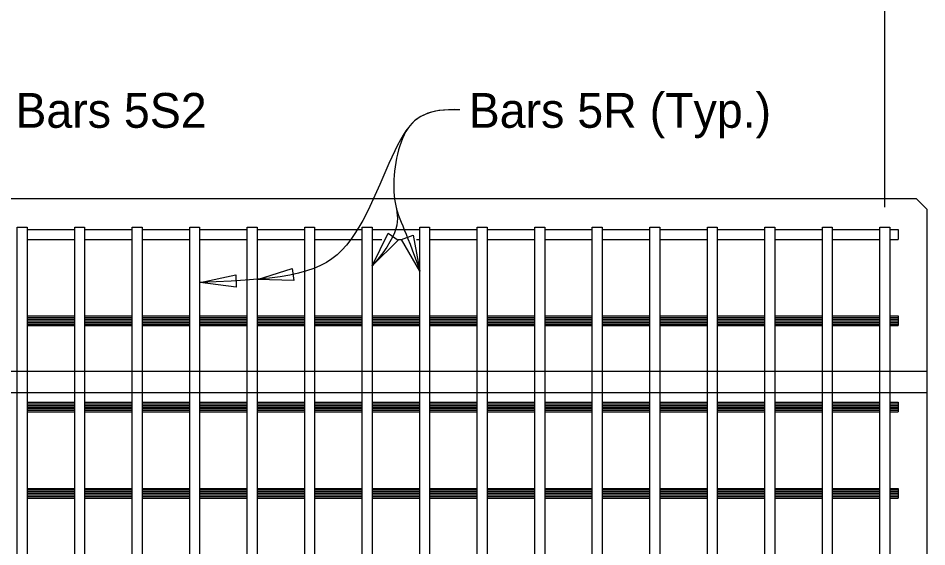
# Model space of a CAD drawing. Extents: x 120587.5 to 120659.6, y 120683.4 to 120715.5.
# Drawn here: x 120592.74 to 120598, y 120702.4 to 120705.47 of the extents above; entities that cross this region are included whole.
import ezdxf

# ---------------------------------------------------------------- set-up
doc = ezdxf.new("R2010")
doc.units = 0
for name, color, linetype in [('AdhocPoint_dp', 7, 'Continuous'), ('Border', 7, 'Continuous'), ('PlotBorder_dp', 7, 'Continuous'), ('TextMisc', 7, 'Continuous')]:
    doc.layers.add(name, color=color, linetype=linetype)

msp = doc.modelspace()

# ---------------------------------------------------------------- linework, layer by layer
at = {"layer": 'AdhocPoint_dp'}
msp.add_line((120597.7581, 120704.3707), (120597.7581, 120706.3004), dxfattribs=at)
for points in [[(120594.7867, 120704.0299), (120594.8793, 120704.2197), (120594.9366, 120704.1786)], [(120595.0627, 120703.9997), (120594.9577, 120704.183), (120595.0239, 120704.2074)], [(120594.1226, 120703.951), (120594.3241, 120704.0146), (120594.3338, 120703.9447)], [(120593.7893, 120703.9341), (120593.996, 120703.9773), (120593.9988, 120703.9068)]]:
    msp.add_lwpolyline(points, close=True, dxfattribs=at)
for points in [[(120595.2949, 120704.9346), (120595.1103, 120704.9415), (120594.9377, 120704.8446), (120594.8852, 120704.3646), (120594.9784, 120704.2515), (120594.7867, 120704.0299)], [(120595.2949, 120704.9346), (120595.1103, 120704.9415), (120594.9377, 120704.8446), (120594.8852, 120704.3646), (120594.9784, 120704.2515), (120595.0627, 120703.9997)], [(120595.2949, 120704.9346), (120595.1197, 120704.9346), (120594.9534, 120704.8972), (120594.6845, 120704.0214), (120594.3179, 120703.952), (120593.7867, 120703.934)]]:
    msp.add_open_spline(points, degree=3, dxfattribs=at)
at = {"layer": 'Border'}
for p, q in [((120592.7867, 120704.2407), (120593.0627, 120704.2407)), ((120593.12, 120704.2407), (120593.3961, 120704.2407)), ((120593.4534, 120704.2407), (120593.7294, 120704.2407)), ((120593.7867, 120704.2407), (120594.0627, 120704.2407)), ((120594.12, 120704.2407), (120594.3961, 120704.2407)), ((120594.4534, 120704.2407), (120594.7294, 120704.2407)), ((120594.7867, 120704.2407), (120595.0627, 120704.2407)), ((120595.12, 120704.2407), (120595.3961, 120704.2407)), ((120595.4534, 120704.2407), (120595.7294, 120704.2407)), ((120595.7867, 120704.2407), (120596.0627, 120704.2407)), ((120596.12, 120704.2407), (120596.3961, 120704.2407)), ((120596.4534, 120704.2407), (120596.7294, 120704.2407)), ((120596.7867, 120704.2407), (120597.0627, 120704.2407)), ((120597.12, 120704.2407), (120597.3961, 120704.2407)), ((120597.4534, 120704.2407), (120597.7294, 120704.2407)), ((120597.7867, 120704.2407), (120597.8349, 120704.2407)), ((120597.8349, 120704.2407), (120597.8349, 120704.1834)), ((120592.7867, 120704.1834), (120593.0627, 120704.1834)), ((120593.12, 120704.1834), (120593.3961, 120704.1834)), ((120593.4534, 120704.1834), (120593.7294, 120704.1834)), ((120593.7867, 120704.1834), (120594.0627, 120704.1834)), ((120594.12, 120704.1834), (120594.3961, 120704.1834)), ((120594.4534, 120704.1834), (120594.7294, 120704.1834)), ((120594.7867, 120704.1834), (120594.8422, 120704.1834)), ((120594.9377, 120704.1834), (120594.9526, 120704.1834)), ((120595.0441, 120704.1834), (120595.0627, 120704.1834)), ((120595.12, 120704.1834), (120595.3961, 120704.1834)), ((120595.4534, 120704.1834), (120595.7294, 120704.1834)), ((120595.7867, 120704.1834), (120596.0627, 120704.1834)), ((120596.12, 120704.1834), (120596.3961, 120704.1834)), ((120596.4534, 120704.1834), (120596.7294, 120704.1834)), ((120596.7867, 120704.1834), (120597.0627, 120704.1834)), ((120597.12, 120704.1834), (120597.3961, 120704.1834)), ((120597.4534, 120704.1834), (120597.7294, 120704.1834)), ((120597.7867, 120704.1834), (120597.8349, 120704.1834)), ((120592.7867, 120703.7407), (120593.0627, 120703.7407)), ((120592.7867, 120703.7311), (120593.0627, 120703.7311)), ((120593.12, 120703.7407), (120593.3961, 120703.7407)), ((120593.12, 120703.7311), (120593.3961, 120703.7311)), ((120593.4534, 120703.7407), (120593.7294, 120703.7407)), ((120593.4534, 120703.7311), (120593.7294, 120703.7311)), ((120593.7867, 120703.7407), (120594.0627, 120703.7407)), ((120593.7867, 120703.7311), (120594.0627, 120703.7311)), ((120594.12, 120703.7407), (120594.3961, 120703.7407)), ((120594.12, 120703.7311), (120594.3961, 120703.7311)), ((120594.4534, 120703.7407), (120594.7294, 120703.7407)), ((120594.4534, 120703.7311), (120594.7294, 120703.7311)), ((120594.7867, 120703.7407), (120595.0627, 120703.7407)), ((120594.7867, 120703.7311), (120595.0627, 120703.7311)), ((120595.12, 120703.7407), (120595.3961, 120703.7407)), ((120595.12, 120703.7311), (120595.3961, 120703.7311)), ((120595.4534, 120703.7407), (120595.7294, 120703.7407)), ((120595.4534, 120703.7311), (120595.7294, 120703.7311)), ((120595.7867, 120703.7407), (120596.0627, 120703.7407)), ((120595.7867, 120703.7311), (120596.0627, 120703.7311)), ((120596.12, 120703.7407), (120596.3961, 120703.7407)), ((120596.12, 120703.7311), (120596.3961, 120703.7311)), ((120596.4534, 120703.7407), (120596.7294, 120703.7407)), ((120596.4534, 120703.7311), (120596.7294, 120703.7311)), ((120596.7867, 120703.7407), (120597.0627, 120703.7407)), ((120596.7867, 120703.7311), (120597.0627, 120703.7311)), ((120597.12, 120703.7407), (120597.3961, 120703.7407)), ((120597.12, 120703.7311), (120597.3961, 120703.7311)), ((120597.4534, 120703.7407), (120597.7294, 120703.7407)), ((120597.4534, 120703.7311), (120597.7294, 120703.7311)), ((120597.7867, 120703.7407), (120597.8349, 120703.7407)), ((120597.7867, 120703.7311), (120597.8349, 120703.7311)), ((120597.8349, 120703.7407), (120597.8349, 120703.6834)), ((120592.7867, 120703.7216), (120593.0627, 120703.7216)), ((120592.7867, 120703.712), (120593.0627, 120703.712)), ((120592.7867, 120703.7025), (120593.0627, 120703.7025)), ((120592.7867, 120703.6929), (120593.0627, 120703.6929)), ((120592.7867, 120703.6834), (120593.0627, 120703.6834)), ((120593.12, 120703.7216), (120593.3961, 120703.7216)), ((120593.12, 120703.712), (120593.3961, 120703.712)), ((120593.12, 120703.7025), (120593.3961, 120703.7025)), ((120593.12, 120703.6929), (120593.3961, 120703.6929)), ((120593.12, 120703.6834), (120593.3961, 120703.6834)), ((120593.4534, 120703.7216), (120593.7294, 120703.7216)), ((120593.4534, 120703.712), (120593.7294, 120703.712)), ((120593.4534, 120703.7025), (120593.7294, 120703.7025)), ((120593.4534, 120703.6929), (120593.7294, 120703.6929)), ((120593.4534, 120703.6834), (120593.7294, 120703.6834)), ((120593.7867, 120703.7216), (120594.0627, 120703.7216)), ((120593.7867, 120703.712), (120594.0627, 120703.712)), ((120593.7867, 120703.7025), (120594.0627, 120703.7025)), ((120593.7867, 120703.6929), (120594.0627, 120703.6929)), ((120593.7867, 120703.6834), (120594.0627, 120703.6834)), ((120594.12, 120703.7216), (120594.3961, 120703.7216)), ((120594.12, 120703.712), (120594.3961, 120703.712)), ((120594.12, 120703.7025), (120594.3961, 120703.7025)), ((120594.12, 120703.6929), (120594.3961, 120703.6929)), ((120594.12, 120703.6834), (120594.3961, 120703.6834)), ((120594.4534, 120703.7216), (120594.7294, 120703.7216)), ((120594.4534, 120703.712), (120594.7294, 120703.712)), ((120594.4534, 120703.7025), (120594.7294, 120703.7025)), ((120594.4534, 120703.6929), (120594.7294, 120703.6929)), ((120594.4534, 120703.6834), (120594.7294, 120703.6834)), ((120594.7867, 120703.7216), (120595.0627, 120703.7216)), ((120594.7867, 120703.712), (120595.0627, 120703.712)), ((120594.7867, 120703.7025), (120595.0627, 120703.7025)), ((120594.7867, 120703.6929), (120595.0627, 120703.6929)), ((120594.7867, 120703.6834), (120595.0627, 120703.6834)), ((120595.12, 120703.7216), (120595.3961, 120703.7216)), ((120595.12, 120703.712), (120595.3961, 120703.712)), ((120595.12, 120703.7025), (120595.3961, 120703.7025)), ((120595.12, 120703.6929), (120595.3961, 120703.6929)), ((120595.12, 120703.6834), (120595.3961, 120703.6834)), ((120595.4534, 120703.7216), (120595.7294, 120703.7216)), ((120595.4534, 120703.712), (120595.7294, 120703.712)), ((120595.4534, 120703.7025), (120595.7294, 120703.7025)), ((120595.4534, 120703.6929), (120595.7294, 120703.6929)), ((120595.4534, 120703.6834), (120595.7294, 120703.6834)), ((120595.7867, 120703.7216), (120596.0627, 120703.7216)), ((120595.7867, 120703.712), (120596.0627, 120703.712)), ((120595.7867, 120703.7025), (120596.0627, 120703.7025)), ((120595.7867, 120703.6929), (120596.0627, 120703.6929)), ((120595.7867, 120703.6834), (120596.0627, 120703.6834)), ((120596.12, 120703.7216), (120596.3961, 120703.7216)), ((120596.12, 120703.712), (120596.3961, 120703.712)), ((120596.12, 120703.7025), (120596.3961, 120703.7025)), ((120596.12, 120703.6929), (120596.3961, 120703.6929)), ((120596.12, 120703.6834), (120596.3961, 120703.6834)), ((120596.4534, 120703.7216), (120596.7294, 120703.7216)), ((120596.4534, 120703.712), (120596.7294, 120703.712)), ((120596.4534, 120703.7025), (120596.7294, 120703.7025)), ((120596.4534, 120703.6929), (120596.7294, 120703.6929)), ((120596.4534, 120703.6834), (120596.7294, 120703.6834)), ((120596.7867, 120703.7216), (120597.0627, 120703.7216)), ((120596.7867, 120703.712), (120597.0627, 120703.712)), ((120596.7867, 120703.7025), (120597.0627, 120703.7025)), ((120596.7867, 120703.6929), (120597.0627, 120703.6929)), ((120596.7867, 120703.6834), (120597.0627, 120703.6834)), ((120597.12, 120703.7216), (120597.3961, 120703.7216)), ((120597.12, 120703.712), (120597.3961, 120703.712)), ((120597.12, 120703.7025), (120597.3961, 120703.7025)), ((120597.12, 120703.6929), (120597.3961, 120703.6929)), ((120597.12, 120703.6834), (120597.3961, 120703.6834)), ((120597.4534, 120703.7216), (120597.7294, 120703.7216)), ((120597.4534, 120703.712), (120597.7294, 120703.712)), ((120597.4534, 120703.7025), (120597.7294, 120703.7025)), ((120597.4534, 120703.6929), (120597.7294, 120703.6929)), ((120597.4534, 120703.6834), (120597.7294, 120703.6834)), ((120597.7867, 120703.7216), (120597.8349, 120703.7216)), ((120597.7867, 120703.712), (120597.8349, 120703.712)), ((120597.7867, 120703.7025), (120597.8349, 120703.7025)), ((120597.7867, 120703.6929), (120597.8349, 120703.6929)), ((120597.7867, 120703.6834), (120597.8349, 120703.6834)), ((120592.7867, 120703.2407), (120593.0627, 120703.2407)), ((120592.7867, 120703.2311), (120593.0627, 120703.2311)), ((120592.7867, 120703.2216), (120593.0627, 120703.2216)), ((120592.7867, 120703.212), (120593.0627, 120703.212)), ((120592.7867, 120703.2025), (120593.0627, 120703.2025)), ((120593.12, 120703.2407), (120593.3961, 120703.2407)), ((120593.12, 120703.2311), (120593.3961, 120703.2311)), ((120593.12, 120703.2216), (120593.3961, 120703.2216)), ((120593.12, 120703.212), (120593.3961, 120703.212)), ((120593.12, 120703.2025), (120593.3961, 120703.2025)), ((120593.4534, 120703.2407), (120593.7294, 120703.2407)), ((120593.4534, 120703.2311), (120593.7294, 120703.2311)), ((120593.4534, 120703.2216), (120593.7294, 120703.2216)), ((120593.4534, 120703.212), (120593.7294, 120703.212)), ((120593.4534, 120703.2025), (120593.7294, 120703.2025)), ((120593.7867, 120703.2407), (120594.0627, 120703.2407)), ((120593.7867, 120703.2311), (120594.0627, 120703.2311)), ((120593.7867, 120703.2216), (120594.0627, 120703.2216)), ((120593.7867, 120703.212), (120594.0627, 120703.212)), ((120593.7867, 120703.2025), (120594.0627, 120703.2025)), ((120594.12, 120703.2407), (120594.3961, 120703.2407)), ((120594.12, 120703.2311), (120594.3961, 120703.2311)), ((120594.12, 120703.2216), (120594.3961, 120703.2216)), ((120594.12, 120703.212), (120594.3961, 120703.212)), ((120594.12, 120703.2025), (120594.3961, 120703.2025)), ((120594.4534, 120703.2407), (120594.7294, 120703.2407)), ((120594.4534, 120703.2311), (120594.7294, 120703.2311)), ((120594.4534, 120703.2216), (120594.7294, 120703.2216)), ((120594.4534, 120703.212), (120594.7294, 120703.212)), ((120594.4534, 120703.2025), (120594.7294, 120703.2025)), ((120594.7867, 120703.2407), (120595.0627, 120703.2407)), ((120594.7867, 120703.2311), (120595.0627, 120703.2311)), ((120594.7867, 120703.2216), (120595.0627, 120703.2216)), ((120594.7867, 120703.212), (120595.0627, 120703.212)), ((120594.7867, 120703.2025), (120595.0627, 120703.2025)), ((120595.12, 120703.2407), (120595.3961, 120703.2407)), ((120595.12, 120703.2311), (120595.3961, 120703.2311)), ((120595.12, 120703.2216), (120595.3961, 120703.2216)), ((120595.12, 120703.212), (120595.3961, 120703.212)), ((120595.12, 120703.2025), (120595.3961, 120703.2025)), ((120595.4534, 120703.2407), (120595.7294, 120703.2407)), ((120595.4534, 120703.2311), (120595.7294, 120703.2311)), ((120595.4534, 120703.2216), (120595.7294, 120703.2216)), ((120595.4534, 120703.212), (120595.7294, 120703.212)), ((120595.4534, 120703.2025), (120595.7294, 120703.2025)), ((120595.7867, 120703.2407), (120596.0627, 120703.2407)), ((120595.7867, 120703.2311), (120596.0627, 120703.2311)), ((120595.7867, 120703.2216), (120596.0627, 120703.2216)), ((120595.7867, 120703.212), (120596.0627, 120703.212)), ((120595.7867, 120703.2025), (120596.0627, 120703.2025)), ((120596.12, 120703.2407), (120596.3961, 120703.2407)), ((120596.12, 120703.2311), (120596.3961, 120703.2311)), ((120596.12, 120703.2216), (120596.3961, 120703.2216)), ((120596.12, 120703.212), (120596.3961, 120703.212)), ((120596.12, 120703.2025), (120596.3961, 120703.2025)), ((120596.4534, 120703.2407), (120596.7294, 120703.2407)), ((120596.4534, 120703.2311), (120596.7294, 120703.2311)), ((120596.4534, 120703.2216), (120596.7294, 120703.2216)), ((120596.4534, 120703.212), (120596.7294, 120703.212)), ((120596.4534, 120703.2025), (120596.7294, 120703.2025)), ((120596.7867, 120703.2407), (120597.0627, 120703.2407)), ((120596.7867, 120703.2311), (120597.0627, 120703.2311)), ((120596.7867, 120703.2216), (120597.0627, 120703.2216)), ((120596.7867, 120703.212), (120597.0627, 120703.212)), ((120596.7867, 120703.2025), (120597.0627, 120703.2025)), ((120597.12, 120703.2407), (120597.3961, 120703.2407)), ((120597.12, 120703.2311), (120597.3961, 120703.2311)), ((120597.12, 120703.2216), (120597.3961, 120703.2216)), ((120597.12, 120703.212), (120597.3961, 120703.212)), ((120597.12, 120703.2025), (120597.3961, 120703.2025)), ((120597.4534, 120703.2407), (120597.7294, 120703.2407)), ((120597.4534, 120703.2311), (120597.7294, 120703.2311)), ((120597.4534, 120703.2216), (120597.7294, 120703.2216)), ((120597.4534, 120703.212), (120597.7294, 120703.212)), ((120597.4534, 120703.2025), (120597.7294, 120703.2025)), ((120597.7867, 120703.2407), (120597.8349, 120703.2407)), ((120597.7867, 120703.2311), (120597.8349, 120703.2311)), ((120597.7867, 120703.2216), (120597.8349, 120703.2216)), ((120597.7867, 120703.212), (120597.8349, 120703.212)), ((120597.7867, 120703.2025), (120597.8349, 120703.2025)), ((120597.8349, 120703.2407), (120597.8349, 120703.1834)), ((120592.7867, 120703.1929), (120593.0627, 120703.1929)), ((120592.7867, 120703.1834), (120593.0627, 120703.1834)), ((120593.12, 120703.1929), (120593.3961, 120703.1929)), ((120593.12, 120703.1834), (120593.3961, 120703.1834)), ((120593.4534, 120703.1929), (120593.7294, 120703.1929)), ((120593.4534, 120703.1834), (120593.7294, 120703.1834)), ((120593.7867, 120703.1929), (120594.0627, 120703.1929)), ((120593.7867, 120703.1834), (120594.0627, 120703.1834)), ((120594.12, 120703.1929), (120594.3961, 120703.1929)), ((120594.12, 120703.1834), (120594.3961, 120703.1834)), ((120594.4534, 120703.1929), (120594.7294, 120703.1929)), ((120594.4534, 120703.1834), (120594.7294, 120703.1834)), ((120594.7867, 120703.1929), (120595.0627, 120703.1929)), ((120594.7867, 120703.1834), (120595.0627, 120703.1834)), ((120595.12, 120703.1929), (120595.3961, 120703.1929)), ((120595.12, 120703.1834), (120595.3961, 120703.1834)), ((120595.4534, 120703.1929), (120595.7294, 120703.1929)), ((120595.4534, 120703.1834), (120595.7294, 120703.1834)), ((120595.7867, 120703.1929), (120596.0627, 120703.1929)), ((120595.7867, 120703.1834), (120596.0627, 120703.1834)), ((120596.12, 120703.1929), (120596.3961, 120703.1929)), ((120596.12, 120703.1834), (120596.3961, 120703.1834)), ((120596.4534, 120703.1929), (120596.7294, 120703.1929)), ((120596.4534, 120703.1834), (120596.7294, 120703.1834)), ((120596.7867, 120703.1929), (120597.0627, 120703.1929)), ((120596.7867, 120703.1834), (120597.0627, 120703.1834)), ((120597.12, 120703.1929), (120597.3961, 120703.1929)), ((120597.12, 120703.1834), (120597.3961, 120703.1834)), ((120597.4534, 120703.1929), (120597.7294, 120703.1929)), ((120597.4534, 120703.1834), (120597.7294, 120703.1834)), ((120597.7867, 120703.1929), (120597.8349, 120703.1929)), ((120597.7867, 120703.1834), (120597.8349, 120703.1834)), ((120592.7867, 120702.7407), (120593.0627, 120702.7407)), ((120592.7867, 120702.7311), (120593.0627, 120702.7311)), ((120593.12, 120702.7407), (120593.3961, 120702.7407)), ((120593.12, 120702.7311), (120593.3961, 120702.7311)), ((120593.4534, 120702.7407), (120593.7294, 120702.7407)), ((120593.4534, 120702.7311), (120593.7294, 120702.7311)), ((120593.7867, 120702.7407), (120594.0627, 120702.7407)), ((120593.7867, 120702.7311), (120594.0627, 120702.7311)), ((120594.12, 120702.7407), (120594.3961, 120702.7407)), ((120594.12, 120702.7311), (120594.3961, 120702.7311)), ((120594.4534, 120702.7407), (120594.7294, 120702.7407)), ((120594.4534, 120702.7311), (120594.7294, 120702.7311)), ((120594.7867, 120702.7407), (120595.0627, 120702.7407)), ((120594.7867, 120702.7311), (120595.0627, 120702.7311)), ((120595.12, 120702.7407), (120595.3961, 120702.7407)), ((120595.12, 120702.7311), (120595.3961, 120702.7311)), ((120595.4534, 120702.7407), (120595.7294, 120702.7407)), ((120595.4534, 120702.7311), (120595.7294, 120702.7311)), ((120595.7867, 120702.7407), (120596.0627, 120702.7407)), ((120595.7867, 120702.7311), (120596.0627, 120702.7311)), ((120596.12, 120702.7407), (120596.3961, 120702.7407)), ((120596.12, 120702.7311), (120596.3961, 120702.7311)), ((120596.4534, 120702.7407), (120596.7294, 120702.7407)), ((120596.4534, 120702.7311), (120596.7294, 120702.7311)), ((120596.7867, 120702.7407), (120597.0627, 120702.7407)), ((120596.7867, 120702.7311), (120597.0627, 120702.7311)), ((120597.12, 120702.7407), (120597.3961, 120702.7407)), ((120597.12, 120702.7311), (120597.3961, 120702.7311)), ((120597.4534, 120702.7407), (120597.7294, 120702.7407)), ((120597.4534, 120702.7311), (120597.7294, 120702.7311)), ((120597.7867, 120702.7407), (120597.8349, 120702.7407)), ((120597.7867, 120702.7311), (120597.8349, 120702.7311)), ((120597.8349, 120702.7407), (120597.8349, 120702.6834)), ((120592.7867, 120702.7216), (120593.0627, 120702.7216)), ((120592.7867, 120702.712), (120593.0627, 120702.712)), ((120592.7867, 120702.7025), (120593.0627, 120702.7025)), ((120592.7867, 120702.6929), (120593.0627, 120702.6929)), ((120592.7867, 120702.6834), (120593.0627, 120702.6834)), ((120593.12, 120702.7216), (120593.3961, 120702.7216)), ((120593.12, 120702.712), (120593.3961, 120702.712)), ((120593.12, 120702.7025), (120593.3961, 120702.7025)), ((120593.12, 120702.6929), (120593.3961, 120702.6929)), ((120593.12, 120702.6834), (120593.3961, 120702.6834)), ((120593.4534, 120702.7216), (120593.7294, 120702.7216)), ((120593.4534, 120702.712), (120593.7294, 120702.712)), ((120593.4534, 120702.7025), (120593.7294, 120702.7025)), ((120593.4534, 120702.6929), (120593.7294, 120702.6929)), ((120593.4534, 120702.6834), (120593.7294, 120702.6834)), ((120593.7867, 120702.7216), (120594.0627, 120702.7216)), ((120593.7867, 120702.712), (120594.0627, 120702.712)), ((120593.7867, 120702.7025), (120594.0627, 120702.7025)), ((120593.7867, 120702.6929), (120594.0627, 120702.6929)), ((120593.7867, 120702.6834), (120594.0627, 120702.6834)), ((120594.12, 120702.7216), (120594.3961, 120702.7216)), ((120594.12, 120702.712), (120594.3961, 120702.712)), ((120594.12, 120702.7025), (120594.3961, 120702.7025)), ((120594.12, 120702.6929), (120594.3961, 120702.6929)), ((120594.12, 120702.6834), (120594.3961, 120702.6834)), ((120594.4534, 120702.7216), (120594.7294, 120702.7216)), ((120594.4534, 120702.712), (120594.7294, 120702.712)), ((120594.4534, 120702.7025), (120594.7294, 120702.7025)), ((120594.4534, 120702.6929), (120594.7294, 120702.6929)), ((120594.4534, 120702.6834), (120594.7294, 120702.6834)), ((120594.7867, 120702.7216), (120595.0627, 120702.7216)), ((120594.7867, 120702.712), (120595.0627, 120702.712)), ((120594.7867, 120702.7025), (120595.0627, 120702.7025)), ((120594.7867, 120702.6929), (120595.0627, 120702.6929)), ((120594.7867, 120702.6834), (120595.0627, 120702.6834)), ((120595.12, 120702.7216), (120595.3961, 120702.7216)), ((120595.12, 120702.712), (120595.3961, 120702.712)), ((120595.12, 120702.7025), (120595.3961, 120702.7025)), ((120595.12, 120702.6929), (120595.3961, 120702.6929)), ((120595.12, 120702.6834), (120595.3961, 120702.6834)), ((120595.4534, 120702.7216), (120595.7294, 120702.7216)), ((120595.4534, 120702.712), (120595.7294, 120702.712)), ((120595.4534, 120702.7025), (120595.7294, 120702.7025)), ((120595.4534, 120702.6929), (120595.7294, 120702.6929)), ((120595.4534, 120702.6834), (120595.7294, 120702.6834)), ((120595.7867, 120702.7216), (120596.0627, 120702.7216)), ((120595.7867, 120702.712), (120596.0627, 120702.712)), ((120595.7867, 120702.7025), (120596.0627, 120702.7025)), ((120595.7867, 120702.6929), (120596.0627, 120702.6929)), ((120595.7867, 120702.6834), (120596.0627, 120702.6834)), ((120596.12, 120702.7216), (120596.3961, 120702.7216)), ((120596.12, 120702.712), (120596.3961, 120702.712)), ((120596.12, 120702.7025), (120596.3961, 120702.7025)), ((120596.12, 120702.6929), (120596.3961, 120702.6929)), ((120596.12, 120702.6834), (120596.3961, 120702.6834)), ((120596.4534, 120702.7216), (120596.7294, 120702.7216)), ((120596.4534, 120702.712), (120596.7294, 120702.712)), ((120596.4534, 120702.7025), (120596.7294, 120702.7025)), ((120596.4534, 120702.6929), (120596.7294, 120702.6929)), ((120596.4534, 120702.6834), (120596.7294, 120702.6834)), ((120596.7867, 120702.7216), (120597.0627, 120702.7216)), ((120596.7867, 120702.712), (120597.0627, 120702.712)), ((120596.7867, 120702.7025), (120597.0627, 120702.7025)), ((120596.7867, 120702.6929), (120597.0627, 120702.6929)), ((120596.7867, 120702.6834), (120597.0627, 120702.6834)), ((120597.12, 120702.7216), (120597.3961, 120702.7216)), ((120597.12, 120702.712), (120597.3961, 120702.712)), ((120597.12, 120702.7025), (120597.3961, 120702.7025)), ((120597.12, 120702.6929), (120597.3961, 120702.6929)), ((120597.12, 120702.6834), (120597.3961, 120702.6834)), ((120597.4534, 120702.7216), (120597.7294, 120702.7216)), ((120597.4534, 120702.712), (120597.7294, 120702.712)), ((120597.4534, 120702.7025), (120597.7294, 120702.7025)), ((120597.4534, 120702.6929), (120597.7294, 120702.6929)), ((120597.4534, 120702.6834), (120597.7294, 120702.6834)), ((120597.7867, 120702.7216), (120597.8349, 120702.7216)), ((120597.7867, 120702.712), (120597.8349, 120702.712)), ((120597.7867, 120702.7025), (120597.8349, 120702.7025)), ((120597.7867, 120702.6929), (120597.8349, 120702.6929)), ((120597.7867, 120702.6834), (120597.8349, 120702.6834))]:
    msp.add_line(p, q, dxfattribs=at)
for points in [[(120592.7294, 120704.2537), (120592.7867, 120704.2537), (120592.7867, 120696.4204), (120592.7294, 120696.4204)], [(120593.0627, 120704.2537), (120593.12, 120704.2537), (120593.12, 120696.4204), (120593.0627, 120696.4204)], [(120593.3961, 120704.2537), (120593.4534, 120704.2537), (120593.4534, 120696.4204), (120593.3961, 120696.4204)], [(120593.7294, 120704.2537), (120593.7867, 120704.2537), (120593.7867, 120696.4204), (120593.7294, 120696.4204)], [(120594.0627, 120704.2537), (120594.12, 120704.2537), (120594.12, 120696.4204), (120594.0627, 120696.4204)], [(120594.3961, 120704.2537), (120594.4534, 120704.2537), (120594.4534, 120696.4204), (120594.3961, 120696.4204)], [(120594.7294, 120704.2537), (120594.7867, 120704.2537), (120594.7867, 120696.4204), (120594.7294, 120696.4204)], [(120595.0627, 120704.2537), (120595.12, 120704.2537), (120595.12, 120696.4204), (120595.0627, 120696.4204)], [(120595.3961, 120704.2537), (120595.4534, 120704.2537), (120595.4534, 120696.4204), (120595.3961, 120696.4204)], [(120595.7294, 120704.2537), (120595.7867, 120704.2537), (120595.7867, 120696.4204), (120595.7294, 120696.4204)], [(120596.0627, 120704.2537), (120596.12, 120704.2537), (120596.12, 120696.4204), (120596.0627, 120696.4204)], [(120596.3961, 120704.2537), (120596.4534, 120704.2537), (120596.4534, 120696.4204), (120596.3961, 120696.4204)], [(120596.7294, 120704.2537), (120596.7867, 120704.2537), (120596.7867, 120696.4204), (120596.7294, 120696.4204)], [(120597.0627, 120704.2537), (120597.12, 120704.2537), (120597.12, 120696.4204), (120597.0627, 120696.4204)], [(120597.3961, 120704.2537), (120597.4534, 120704.2537), (120597.4534, 120696.4204), (120597.3961, 120696.4204)], [(120597.7294, 120704.2537), (120597.7867, 120704.2537), (120597.7867, 120696.4204), (120597.7294, 120696.4204)]]:
    msp.add_lwpolyline(points, close=True, dxfattribs=at)
at = {"layer": 'PlotBorder_dp'}
for p, q in [((120590.328, 120704.4203), (120597.939, 120704.4203)), ((120597.939, 120704.4203), (120598.0015, 120704.3578)), ((120598.0015, 120704.3578), (120598.0015, 120696.4204)), ((120592.3653, 120703.4203), (120598.0015, 120703.4203)), ((120592.3653, 120703.2953), (120598.0015, 120703.2953))]:
    msp.add_line(p, q, dxfattribs=at)

# ---------------------------------------------------------------- texts
at = {"layer": 'TextMisc'}
for s, p in [('Bars 5S2', (120592.7189, 120704.83)), ('Bars 5R (Typ.)', (120595.3464, 120704.83))]:
    msp.add_text(s, height=0.2016, dxfattribs=at).set_placement(p)

doc.saveas('drawing.dxf')
